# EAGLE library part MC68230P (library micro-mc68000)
68xxx PROCESSOR
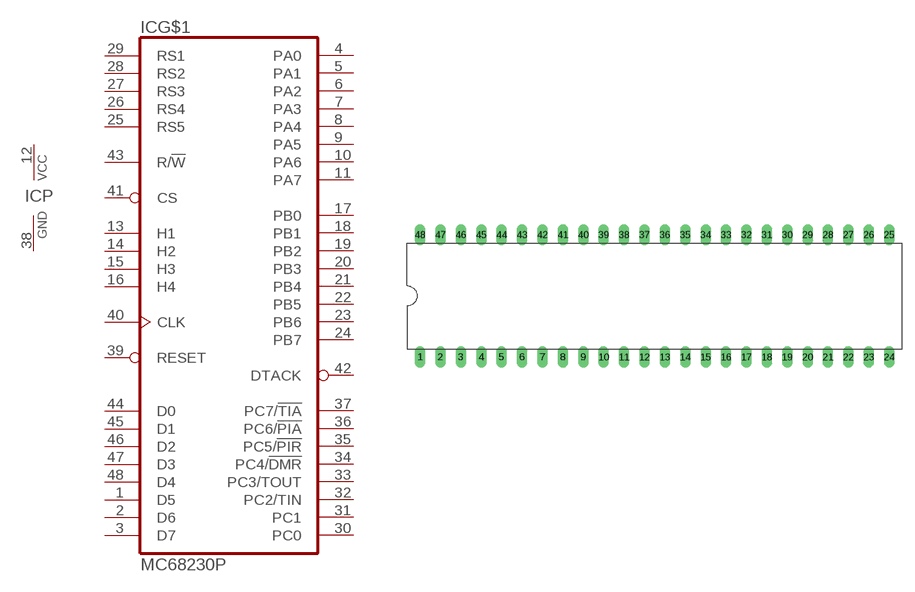
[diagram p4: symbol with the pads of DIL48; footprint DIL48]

Designator prefix IC; gates G$1=68230 P=PWRN

## MC68230P (OC_FARNELL: unknown; OC_NEWARK: unknown)  [DIL48]
1  G$1:D5
2  G$1:D6
3  G$1:D7
4  G$1:PA0
5  G$1:PA1
6  G$1:PA2
7  G$1:PA3
8  G$1:PA4
9  G$1:PA5
10  G$1:PA6
11  G$1:PA7
12  P:VCC  pwr
13  G$1:H1  in
14  G$1:H2
15  G$1:H3  in
16  G$1:H4
17  G$1:PB0
18  G$1:PB1
19  G$1:PB2
20  G$1:PB3
21  G$1:PB4
22  G$1:PB5
23  G$1:PB6
24  G$1:PB7
25  G$1:RS5  in
26  G$1:RS4  in
27  G$1:RS3  in
28  G$1:RS2  in
29  G$1:RS1  in
30  G$1:PC0
31  G$1:PC1
32  G$1:PC2/TIN
33  G$1:PC3/TOUT
34  G$1:PC4/!DMR
35  G$1:PC5/!PIR
36  G$1:PC6/!PIA
37  G$1:PC7/!TIA
38  P:GND  pwr
39  G$1:RESET  in
40  G$1:CLK  in
41  G$1:CS  in
42  G$1:DTACK  out
43  G$1:R/!W  in
44  G$1:D0
45  G$1:D1
46  G$1:D2
47  G$1:D3
48  G$1:D4

## Footprint DIL48 (pad centres in mm)
Dual In Line
drill 0.813 long: 1 -29.21,-7.62; 2 -26.67,-7.62; 3 -24.13,-7.62; 4 -21.59,-7.62; 5 -19.05,-7.62; 6 -16.51,-7.62; 7 -13.97,-7.62; 8 -11.43,-7.62; 9 -8.89,-7.62; 10 -6.35,-7.62; 11 -3.81,-7.62; 12 -1.27,-7.62; 13 1.27,-7.62; 14 3.81,-7.62; 15 6.35,-7.62; 16 8.89,-7.62; 17 11.43,-7.62; 18 13.97,-7.62; 19 16.51,-7.62; 20 19.05,-7.62; 21 21.59,-7.62; 22 24.13,-7.62; 23 26.67,-7.62; 24 29.21,-7.62; 25 29.21,7.62; 26 26.67,7.62; 27 24.13,7.62; 28 21.59,7.62; 29 19.05,7.62; 30 16.51,7.62; 31 13.97,7.62; 32 11.43,7.62; 33 8.89,7.62; 34 6.35,7.62; 35 3.81,7.62; 36 1.27,7.62; 37 -1.27,7.62; 38 -3.81,7.62; 39 -6.35,7.62; 40 -8.89,7.62; 41 -11.43,7.62; 42 -13.97,7.62; 43 -16.51,7.62; 44 -19.05,7.62; 45 -21.59,7.62; 46 -24.13,7.62; 47 -26.67,7.62; 48 -29.21,7.62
